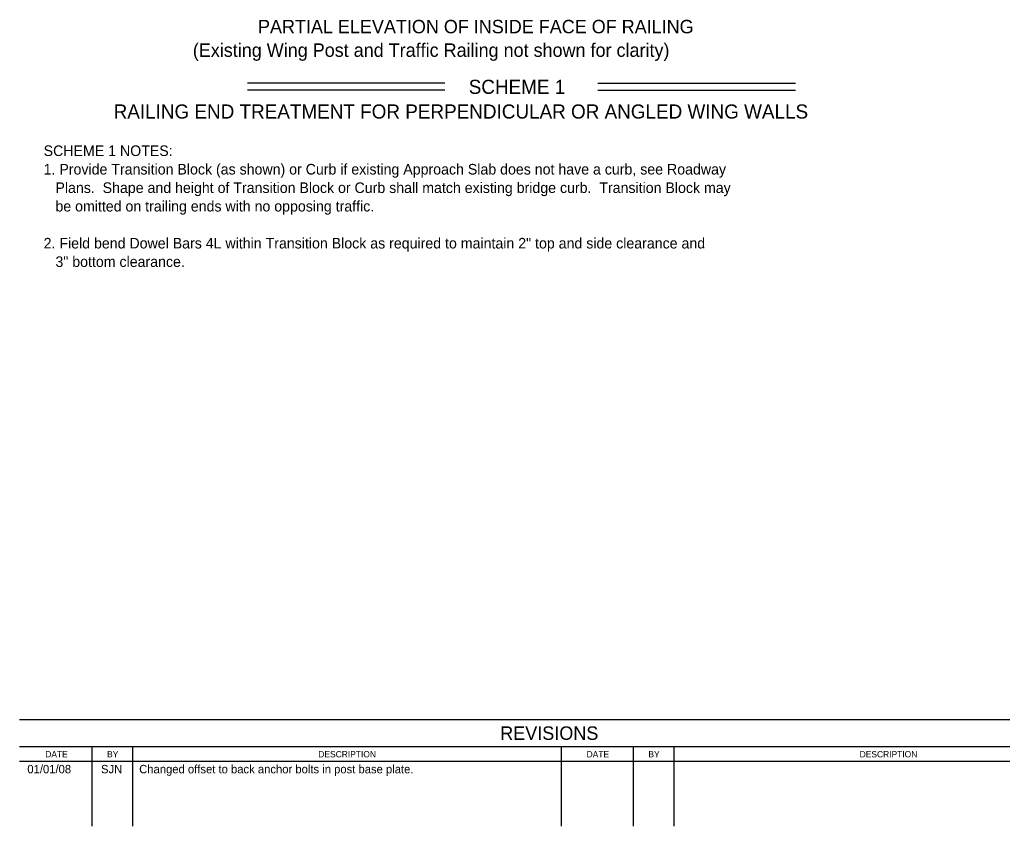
# Model space of a CAD drawing. Extents: x 21526.6 to 21595.9, y 56117 to 56157.3.
# Drawn here: x 21526.6 to 21545.31, y 56116.99 to 56132.35 of the extents above; entities that cross this region are included whole.
import ezdxf

# ---------------------------------------------------------------- set-up
doc = ezdxf.new("R2010")
doc.units = 0
doc.layers.add('Border', color=7, linetype='Continuous')
doc.layers.add('PlotBorder_dp', color=7, linetype='Continuous')

msp = doc.modelspace()

# ---------------------------------------------------------------- linework, layer by layer
at = {"layer": 'Border'}
for p, q in [((21547.212, 56119.023), (21526.6, 56119.023)), ((21547.212, 56118.507), (21526.6, 56118.507)), ((21527.977, 56118.507), (21527.977, 56116.993)), ((21528.751, 56118.507), (21528.751, 56116.993)), ((21536.907, 56118.507), (21536.907, 56116.993)), ((21538.283, 56118.507), (21538.283, 56116.993)), ((21539.057, 56118.507), (21539.057, 56116.993)), ((21526.6, 56118.234), (21547.212, 56118.234))]:
    msp.add_line(p, q, dxfattribs=at)
at = {"layer": 'PlotBorder_dp'}
for p, q in [((21534.695, 56131.142), (21530.937, 56131.142)), ((21537.611, 56131.142), (21541.369, 56131.142)), ((21534.695, 56131.009), (21530.937, 56131.009)), ((21537.611, 56131.009), (21541.369, 56131.009))]:
    msp.add_line(p, q, dxfattribs=at)

# ---------------------------------------------------------------- texts
at = {"layer": 'Border'}
for s, height, p in [('REVISIONS', 0.2567, (21535.749, 56118.639)), ('BY', 0.1201, (21528.265, 56118.305)), ('BY', 0.1201, (21538.571, 56118.305)), ('01/01/08', 0.16, (21526.747, 56118.002)), ('SJN', 0.16, (21528.149, 56118.002)), ('Changed offset to back anchor bolts in post base plate.', 0.16, (21528.876, 56118.002))]:
    msp.add_text(s, height=height, dxfattribs=at).set_placement(p)
for s, height, rotation, p in [('DATE', 0.1196, 359.8693, (21527.089, 56118.306)), ('DESCRIPTION', 0.12007, 0.0498, (21532.287, 56118.305)), ('DATE', 0.1196, 359.8693, (21537.395, 56118.306)), ('DESCRIPTION', 0.12007, 0.0498, (21542.593, 56118.305))]:
    msp.add_text(s, height=height, rotation=rotation, dxfattribs=at).set_placement(p)
at = {"layer": 'PlotBorder_dp'}
for s, height, p in [('PARTIAL ELEVATION OF INSIDE FACE OF RAILING', 0.256, (21531.138, 56132.089)), ('(Existing Wing Post and Traffic Railing not shown for clarity)', 0.256, (21529.897, 56131.641)), ('SCHEME 1', 0.2688, (21535.15, 56130.936)), ('RAILING END TREATMENT FOR PERPENDICULAR OR ANGLED WING WALLS', 0.2688, (21528.39, 56130.466)), ('SCHEME 1 NOTES:', 0.2016, (21527.057, 56129.753)), ('1. Provide Transition Block (as shown) or Curb if existing Approach Slab does not have a curb, see Roadway ', 0.2016, (21527.057, 56129.401)), ('   Plans.  Shape and height of Transition Block or Curb shall match existing bridge curb.  Transition Block may ', 0.2016, (21527.057, 56129.049)), ('   be omitted on trailing ends with no opposing traffic.', 0.2016, (21527.057, 56128.697)), ('2. Field bend Dowel Bars 4L within Transition Block as required to maintain 2" top and side clearance and ', 0.2016, (21527.057, 56127.993)), ('   3" bottom clearance.', 0.2016, (21527.057, 56127.641))]:
    msp.add_text(s, height=height, dxfattribs=at).set_placement(p)

doc.saveas('drawing.dxf')
